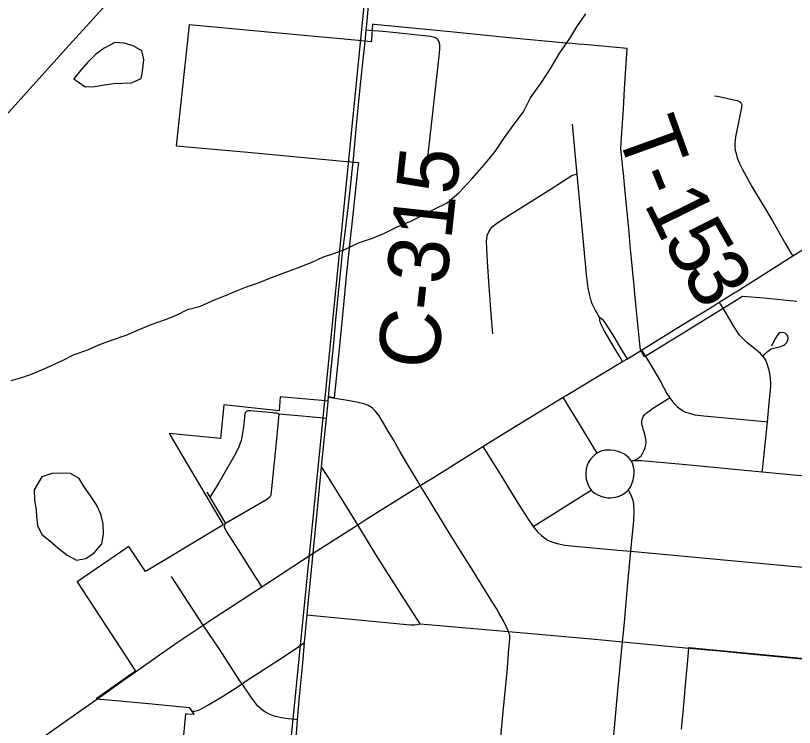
# Model space of a CAD drawing. Extents: x 0 to 34, y 0 to 22.
# Drawn here: x 2.542 to 3.271, y 14.717 to 15.383 of the extents above; entities that cross this region are included whole.
import ezdxf

# ---------------------------------------------------------------- set-up
doc = ezdxf.new("R2010")
doc.units = 0
for name, color, linetype in [('Default', 7, 'Continuous'), ('GM_X_City_Street', 7, 'Continuous'), ('GM_X_County_Road', 7, 'Continuous'), ('GM_X_County_Road_Text', 7, 'Continuous'), ('GM_X_Minor_Lake', 7, 'Continuous'), ('GM_X_Minor_River', 7, 'Continuous'), ('GM_X_Rail_Line', 7, 'Continuous'), ('GM_X_Section', 7, 'Continuous'), ('GM_X_Township_Road', 7, 'Continuous'), ('GM_X_Township_Road_Text', 7, 'Continuous'), ('SC_Shading1', 7, 'Continuous')]:
    doc.layers.add(name, color=color, linetype=linetype)

msp = doc.modelspace()

# ---------------------------------------------------------------- linework, layer by layer
at = {"layer": 'Default'}
msp.add_lwpolyline([(2.1, 15.58132), (2.1, 14.55888), (2.77821, 14.493), (2.87773, 15.48948)], close=True, dxfattribs=at)
at = {"layer": 'GM_X_City_Street'}
for p, q in [((2.72057, 14.93734), (2.72348, 14.93264)), ((2.72348, 14.93264), (2.73823, 14.90802))]:
    msp.add_line(p, q, dxfattribs=at)
for points in [[(2.86984, 15.36994), (2.87292, 15.36966), (2.88536, 15.36855), (2.89481, 15.36771), (2.92433, 15.36462), (2.93009, 15.3638), (2.93241, 15.36331), (2.93407, 15.36278)], [(2.92723, 15.24404), (2.92794, 15.25327), (2.93822, 15.34534), (2.93884, 15.35148), (2.93891, 15.35405), (2.93869, 15.35591), (2.93838, 15.35745), (2.9378, 15.35927), (2.93748, 15.35998), (2.93689, 15.36081), (2.93618, 15.36146), (2.93543, 15.36202), (2.93407, 15.36278)], [(3.08812, 15.10052), (3.0842, 15.10771), (3.0815, 15.11336), (3.08041, 15.1163), (3.07874, 15.12233), (3.07764, 15.12846), (3.07615, 15.14078), (3.07325, 15.1715), (3.06952, 15.21143), (3.06727, 15.23483), (3.0654, 15.25446), (3.06317, 15.27856), (3.06293, 15.28156)], [(2.98848, 15.08527), (2.98753, 15.09648), (2.98633, 15.11235), (2.98478, 15.13433), (2.98351, 15.15294), (2.98253, 15.17178), (2.98271, 15.17488), (2.98337, 15.1779), (2.98455, 15.18078), (2.98614, 15.18344), (2.98817, 15.18578), (2.99059, 15.18774), (2.99315, 15.1895), (3.00354, 15.19631), (3.04299, 15.22112), (3.06234, 15.2335), (3.06409, 15.23406), (3.0664, 15.23462), (3.06727, 15.23483)], [(3.24069, 14.95626), (3.24084, 14.95768), (3.2454, 15.00303), (3.24715, 15.02046), (3.24852, 15.03626), (3.24852, 15.03973), (3.24831, 15.043), (3.24811, 15.04658), (3.24705, 15.05122), (3.24631, 15.05427), (3.24537, 15.05723), (3.24389, 15.06059), (3.24273, 15.0626), (3.24126, 15.0646), (3.23907, 15.06686), (3.23512, 15.07016), (3.23091, 15.07344), (3.22577, 15.07766), (3.22182, 15.08148), (3.21945, 15.08398), (3.2164, 15.08841), (3.21366, 15.09294), (3.20589, 15.1064), (3.20234, 15.11189), (3.2004, 15.11488)], [(3.11438, 15.06209), (3.1119, 15.06606), (3.10866, 15.07124), (3.10071, 15.08459), (3.0932, 15.09626), (3.09202, 15.09776), (3.09035, 15.09911), (3.08812, 15.10052)], [(3.10983, 15.05936), (3.10722, 15.06384), (3.10207, 15.07268), (3.09573, 15.08312), (3.0927, 15.08851), (3.08987, 15.09424), (3.08889, 15.0965), (3.08846, 15.09806), (3.08812, 15.10052)], [(3.24126, 15.0646), (3.2451, 15.06842), (3.24679, 15.06979), (3.24822, 15.07092), (3.25029, 15.0716), (3.25409, 15.07252), (3.25766, 15.0736), (3.26015, 15.07454), (3.26165, 15.07535), (3.26271, 15.07628), (3.26365, 15.07741), (3.26434, 15.07897), (3.26475, 15.08066), (3.26484, 15.08166), (3.26447, 15.08309), (3.26353, 15.08453), (3.26196, 15.08584), (3.26071, 15.08641), (3.25915, 15.08665), (3.25721, 15.08634), (3.25578, 15.08541), (3.25447, 15.08378), (3.25297, 15.08141), (3.25141, 15.07847), (3.24922, 15.07379)], [(3.12772, 15.07008), (3.13604, 15.05669), (3.14529, 15.04074), (3.15138, 15.02966), (3.154, 15.02561), (3.15478, 15.0244), (3.15744, 15.02077), (3.16082, 15.01738), (3.16325, 15.01545), (3.16651, 15.01339), (3.16892, 15.01219), (3.1734, 15.01074), (3.17751, 15.00965), (3.18609, 15.00854), (3.24317, 15.00324), (3.2454, 15.00303)], [(2.92048, 14.9433), (2.91787, 14.94772), (2.90801, 14.96434), (2.9017, 14.97486), (2.89724, 14.98274), (2.89597, 14.98517), (2.89124, 14.99269), (2.88513, 15.00348), (2.88189, 15.0087), (2.87829, 15.0132), (2.87541, 15.01608), (2.87181, 15.01842), (2.86786, 15.01986), (2.86084, 15.02147), (2.85239, 15.02291), (2.84073, 15.02485), (2.83453, 15.02585)], [(3.08616, 14.97376), (3.08274, 14.97939), (3.0698, 15.0006), (3.05835, 15.01926), (3.05424, 15.02595)], [(3.11798, 14.9664), (3.12181, 14.96761), (3.12422, 14.96872), (3.12573, 14.96982), (3.12724, 14.97123), (3.12855, 14.97328), (3.12987, 14.97593), (3.13093, 14.97883), (3.13159, 14.98148), (3.13185, 14.98465), (3.13167, 14.98662), (3.13146, 14.98862), (3.13, 14.99347), (3.12921, 14.99615), (3.12867, 14.99792), (3.12815, 14.99959), (3.1279, 15.00126), (3.12785, 15.00278), (3.12796, 15.00382), (3.12832, 15.00534), (3.12885, 15.0067), (3.12952, 15.00821), (3.13062, 15.00978), (3.13159, 15.01083), (3.13313, 15.01219), (3.13883, 15.01604), (3.15049, 15.0234), (3.15195, 15.02431), (3.154, 15.02561)], [(2.78796, 15.01015), (2.7871, 15.01075), (2.78647, 15.01098), (2.78371, 15.01128), (2.78224, 15.01144), (2.77555, 15.01212), (2.76149, 15.01346), (2.76017, 15.01343), (2.7588, 15.01326), (2.75796, 15.01287), (2.75744, 15.01244), (2.75694, 15.01191), (2.75642, 15.01101), (2.75614, 15.01008), (2.75601, 15.009), (2.75588, 15.00738), (2.75502, 14.99799), (2.75352, 14.98861), (2.75271, 14.98551), (2.75053, 14.97951), (2.74778, 14.97378), (2.73205, 14.94653), (2.72709, 14.93849), (2.72348, 14.93264)], [(2.78796, 15.01015), (2.78553, 14.98359), (2.78452, 14.97444), (2.78355, 14.96526), (2.7811, 14.94063), (2.78062, 14.93426)], [(2.8325, 15.00606), (2.8298, 15.00632), (2.80622, 15.0085), (2.78796, 15.01015)], [(2.97905, 14.97987), (2.98214, 14.97494), (2.9969, 14.95145), (3.00649, 14.93554), (3.01297, 14.92502), (3.02136, 14.91201), (3.02617, 14.9051), (3.03017, 14.90011), (3.03398, 14.89653), (3.03672, 14.89451), (3.03934, 14.89272), (3.04172, 14.89129), (3.04535, 14.88999), (3.04863, 14.88915), (3.05578, 14.88772), (3.06471, 14.88664), (3.10564, 14.88299), (3.11769, 14.88194), (3.12074, 14.88168), (3.25836, 14.86879), (3.32859, 14.86219)], [(3.11552, 14.93953), (3.117, 14.94163), (3.11764, 14.94263), (3.11889, 14.94579), (3.11984, 14.94885), (3.12032, 14.95182), (3.12061, 14.95479), (3.12061, 14.95804), (3.12005, 14.96103), (3.11908, 14.96439), (3.11798, 14.9664), (3.11711, 14.96784), (3.11529, 14.96976), (3.11295, 14.97172), (3.11104, 14.97296), (3.10836, 14.9743), (3.10559, 14.97526), (3.10195, 14.97612), (3.09898, 14.9765), (3.0963, 14.9766), (3.09324, 14.97641), (3.08954, 14.97546), (3.08674, 14.97416), (3.08616, 14.97376), (3.0842, 14.97242), (3.08189, 14.97038), (3.08023, 14.96847), (3.07855, 14.96611), (3.07774, 14.96454), (3.0766, 14.96225), (3.07583, 14.95899), (3.07554, 14.95574), (3.07535, 14.95277), (3.07583, 14.94942), (3.07669, 14.94656), (3.07774, 14.94378), (3.07909, 14.94101), (3.0805, 14.93919), (3.08109, 14.93843), (3.08349, 14.93641), (3.08607, 14.93498), (3.08942, 14.93354), (3.09267, 14.93249), (3.09602, 14.93201), (3.0985, 14.93201), (3.1009, 14.93211), (3.10367, 14.93259), (3.10655, 14.93345), (3.10884, 14.9345), (3.11085, 14.93556), (3.11229, 14.93661), (3.11439, 14.93833), (3.11552, 14.93953)], [(3.11798, 14.9664), (3.12332, 14.9669), (3.12764, 14.96671), (3.13087, 14.96656), (3.13797, 14.96591), (3.16589, 14.96328), (3.24069, 14.95626), (3.33634, 14.94729), (3.3424, 14.94669), (3.38456, 14.94257), (3.39787, 14.94121), (3.40611, 14.94046), (3.46163, 14.9351), (3.46394, 14.93487)], [(2.86192, 14.90671), (2.85944, 14.91074), (2.8484, 14.92875), (2.83549, 14.94926), (2.83386, 14.9518), (2.82803, 14.96085)], [(2.99332, 14.6816), (2.99828, 14.73508), (3.0017, 14.76908), (3.0035, 14.79066), (3.00444, 14.79954), (3.00424, 14.80281), (3.00338, 14.80597), (3.00307, 14.80674), (3.00188, 14.80973), (2.99846, 14.81675), (2.99415, 14.82431), (2.99182, 14.82821), (2.98692, 14.83614), (2.96731, 14.86782), (2.96439, 14.87243), (2.95685, 14.88418), (2.94749, 14.89917), (2.92809, 14.93098), (2.92048, 14.9433)], [(3.02617, 14.9051), (3.02772, 14.90607), (3.07885, 14.93815), (3.0805, 14.93919)], [(3.08194, 14.4989), (3.08214, 14.50093), (3.08902, 14.57127), (3.08975, 14.57917), (3.09716, 14.65989), (3.09942, 14.68453), (3.1021, 14.71334), (3.10453, 14.74119), (3.10805, 14.77778), (3.10994, 14.79718), (3.11166, 14.81528), (3.11447, 14.84885), (3.11769, 14.88194), (3.11925, 14.89808), (3.12028, 14.91046), (3.12066, 14.91918), (3.12031, 14.92602), (3.11963, 14.9295), (3.11832, 14.93344), (3.11672, 14.9369), (3.11552, 14.93953)], [(2.78062, 14.93426), (2.77948, 14.9326), (2.7775, 14.93073), (2.73823, 14.90802)], [(2.77204, 14.84868), (2.76854, 14.85422), (2.7661, 14.85809), (2.75027, 14.88319), (2.74197, 14.89628), (2.7385, 14.90175), (2.73768, 14.90323), (2.73723, 14.90423), (2.73703, 14.90498), (2.73705, 14.90605), (2.73733, 14.90699), (2.73823, 14.90802)], [(2.92031, 14.8139), (2.90342, 14.84014), (2.88866, 14.8635), (2.87877, 14.87889), (2.86192, 14.90671)], [(2.71731, 14.81283), (2.70314, 14.83433), (2.69427, 14.8476), (2.68749, 14.85842)], [(2.8146, 14.82231), (2.82053, 14.82175), (2.89813, 14.81438), (2.90778, 14.81346), (2.91169, 14.81314), (2.91506, 14.81314), (2.91757, 14.81336), (2.92031, 14.8139)], [(2.80562, 14.72418), (2.8035, 14.7244), (2.79666, 14.72509), (2.79042, 14.72606), (2.78484, 14.72725), (2.78128, 14.72858), (2.77842, 14.7298), (2.77568, 14.73126), (2.77309, 14.73298), (2.77068, 14.73493), (2.76844, 14.7371), (2.76638, 14.73943), (2.76265, 14.74439), (2.75354, 14.7579), (2.75223, 14.75985), (2.73184, 14.79108), (2.71731, 14.81283)], [(2.92031, 14.8139), (3.00307, 14.80674), (3.04551, 14.8031), (3.0874, 14.79929), (3.10994, 14.79718), (3.17227, 14.79122)], [(2.7064, 14.73215), (2.70918, 14.73227), (2.71185, 14.73285), (2.7144, 14.73378), (2.72102, 14.73761), (2.73367, 14.74515), (2.7447, 14.752), (2.75354, 14.7579), (2.75661, 14.75994), (2.78811, 14.78044), (2.80352, 14.79075), (2.81219, 14.79654)]]:
    msp.add_lwpolyline(points, dxfattribs=at)
at = {"layer": 'GM_X_County_Road'}
for p, q in [((3.11438, 15.06209), (3.12772, 15.07008)), ((3.10983, 15.05936), (3.11438, 15.06209)), ((2.83431, 15.02383), (2.83453, 15.02585)), ((2.82023, 14.88026), (2.86192, 14.90671)), ((2.77204, 14.84868), (2.82023, 14.88026)), ((2.81219, 14.79654), (2.8146, 14.82231))]:
    msp.add_line(p, q, dxfattribs=at)
for points in [[(3.26918, 15.15837), (3.3118, 15.18484), (3.33823, 15.20119), (3.36749, 15.21887), (3.39692, 15.23621), (3.42364, 15.25205), (3.47295, 15.28086), (3.48991, 15.29036), (3.55312, 15.32589), (3.64279, 15.37547), (3.66715, 15.38906), (3.7813, 15.45258), (3.84384, 15.48767), (3.90317, 15.52055), (3.90579, 15.522)], [(2.86984, 15.36994), (2.87032, 15.37487), (2.87319, 15.40688), (2.87706, 15.44438)], [(2.86704, 15.3421), (2.86875, 15.35876), (2.86984, 15.36994)], [(2.85739, 15.24364), (2.85761, 15.24563), (2.86114, 15.2839), (2.86203, 15.29344), (2.86368, 15.30926), (2.86493, 15.32152), (2.86704, 15.3421)], [(2.8531, 15.20589), (2.85478, 15.21985), (2.85739, 15.24364)], [(2.83942, 15.0766), (2.84153, 15.09883), (2.84528, 15.13599), (2.84777, 15.16081), (2.84998, 15.17996), (2.8531, 15.20589)], [(3.2004, 15.11488), (3.21508, 15.12397), (3.21612, 15.12464), (3.26225, 15.15407), (3.26918, 15.15837)], [(3.12772, 15.07008), (3.16733, 15.09457), (3.1936, 15.11068), (3.2004, 15.11488)], [(2.83453, 15.02585), (2.83547, 15.03662), (2.83855, 15.06751), (2.83942, 15.0766)], [(3.05424, 15.02595), (3.05697, 15.02761), (3.10983, 15.05936)], [(2.8325, 15.00606), (2.8341, 15.02181), (2.83431, 15.02383)], [(2.97905, 14.97987), (2.99968, 14.9927), (3.05424, 15.02595)], [(2.82803, 14.96085), (2.83069, 14.98833), (2.8325, 15.00606)], [(2.92048, 14.9433), (2.93289, 14.951), (2.97905, 14.97987)], [(2.82023, 14.88026), (2.8239, 14.91806), (2.82803, 14.96085)], [(2.86192, 14.90671), (2.87044, 14.91212), (2.92048, 14.9433)], [(2.8146, 14.82231), (2.81589, 14.83611), (2.82023, 14.88026)], [(2.71731, 14.81283), (2.72761, 14.81957), (2.77204, 14.84868)], [(2.68645, 14.79208), (2.69279, 14.79649), (2.71731, 14.81283)], [(2.80562, 14.72418), (2.80745, 14.74613), (2.8104, 14.7773), (2.81219, 14.79654)], [(2.64252, 14.76123), (2.64661, 14.76415), (2.6538, 14.76917), (2.67615, 14.78491), (2.68645, 14.79208)], [(2.60082, 14.73164), (2.61715, 14.74311), (2.64252, 14.76123)], [(2.54356, 14.69123), (2.56895, 14.70926), (2.60082, 14.73164)], [(2.80207, 14.68639), (2.80487, 14.71506), (2.80562, 14.72418)]]:
    msp.add_lwpolyline(points, dxfattribs=at)
at = {"layer": 'GM_X_Minor_Lake'}
for points in [[(2.65993, 15.32889), (2.66077, 15.33374), (2.66164, 15.34208), (2.65983, 15.35008), (2.65153, 15.35474), (2.64321, 15.3575), (2.63448, 15.35799), (2.62454, 15.3528), (2.61649, 15.34682), (2.60918, 15.3397), (2.60225, 15.33181), (2.59607, 15.32391)], [(2.59607, 15.32391), (2.60662, 15.31657), (2.61574, 15.31684), (2.62449, 15.31825), (2.63363, 15.31965), (2.64161, 15.31993), (2.64997, 15.32021), (2.65914, 15.32427), (2.65993, 15.32889)], [(2.56603, 14.95146), (2.55904, 14.93939), (2.5593, 14.9299), (2.56071, 14.92039), (2.56102, 14.91469), (2.56205, 14.90595), (2.56612, 14.89754), (2.57365, 14.89175), (2.58117, 14.88521), (2.58982, 14.87826), (2.5985, 14.8736), (2.60401, 14.87449)], [(2.60401, 14.87449), (2.60725, 14.87501), (2.6153, 14.88061), (2.62224, 14.88887), (2.62387, 14.89796), (2.62361, 14.90746), (2.62144, 14.9166), (2.61737, 14.92538), (2.61178, 14.9338), (2.6058, 14.94223), (2.60096, 14.94988), (2.59304, 14.95454), (2.58317, 14.95504), (2.57557, 14.95475), (2.56603, 14.95146)]]:
    msp.add_lwpolyline(points, dxfattribs=at)
at = {"layer": 'GM_X_Minor_River'}
msp.add_lwpolyline([(2.53751, 15.04179), (2.54818, 15.04469), (2.55811, 15.04837), (2.57109, 15.0539), (2.58561, 15.06056), (2.59631, 15.06612), (2.60928, 15.07051), (2.61959, 15.07494), (2.63143, 15.07935), (2.64516, 15.08412), (2.65509, 15.08855), (2.66846, 15.09408), (2.68181, 15.09885), (2.69212, 15.10289), (2.70244, 15.10808), (2.71464, 15.11135), (2.72763, 15.11726), (2.73793, 15.12131), (2.74824, 15.12574), (2.75779, 15.12942), (2.76885, 15.13307), (2.77954, 15.1375), (2.79442, 15.14301), (2.80549, 15.14705), (2.81923, 15.15257), (2.82993, 15.15737), (2.83947, 15.16067), (2.85053, 15.16471), (2.86276, 15.17063), (2.87573, 15.17503), (2.88681, 15.17945), (2.89866, 15.18537), (2.91164, 15.19091), (2.92158, 15.19572), (2.93343, 15.20203), (2.94566, 15.20795), (2.9568, 15.21768), (2.96912, 15.23082), (2.98067, 15.24396), (2.9907, 15.25599), (2.99922, 15.26917), (3.00849, 15.28159), (3.01699, 15.29325), (3.02361, 15.30608), (3.03443, 15.32151), (3.04295, 15.3347), (3.0511, 15.34826), (3.06038, 15.36182), (3.06698, 15.37275), (3.07548, 15.38479)], dxfattribs=at)
at = {"layer": 'GM_X_Rail_Line'}
msp.add_lwpolyline([(2.1, 14.81172), (2.21342, 14.93725), (2.27041, 15.00196), (2.29876, 15.03142), (2.33999, 15.07735), (2.43241, 15.17961), (2.5269, 15.28373), (2.5887, 15.3522), (2.6494, 15.41902), (2.66788, 15.43827), (2.7067, 15.47633), (2.73284, 15.50225), (2.77572, 15.53539), (2.80161, 15.55513), (2.84301, 15.58439), (2.90313, 15.62543), (2.932, 15.64588)], dxfattribs=at)
at = {"layer": 'GM_X_Section'}
msp.add_lwpolyline([(2.87773, 15.48948), (3.88999, 15.39575), (3.78848, 14.39294), (2.80014, 14.49076), (2.77821, 14.493)], close=True, dxfattribs=at)
at = {"layer": 'GM_X_Township_Road'}
for points in [[(3.19592, 15.30819), (3.19841, 15.30779), (3.20161, 15.30722), (3.21686, 15.3038), (3.21932, 15.30285), (3.22052, 15.30171), (3.22117, 15.30074), (3.22149, 15.29937), (3.22127, 15.29709), (3.21856, 15.28487), (3.21732, 15.27878), (3.21558, 15.26958), (3.21503, 15.26336), (3.21504, 15.26023), (3.21538, 15.25714), (3.21606, 15.25409), (3.21695, 15.25109), (3.21912, 15.24528), (3.22183, 15.23969), (3.23103, 15.22337), (3.25021, 15.19119), (3.26253, 15.16948), (3.26785, 15.16059), (3.26918, 15.15837)], [(3.17227, 14.79122), (3.20081, 14.7886), (3.22554, 14.7862), (3.26454, 14.7825), (3.32699, 14.77676)]]:
    msp.add_lwpolyline(points, dxfattribs=at)
at = {"layer": 'SC_Shading1'}
for points in [[(3.27309, 15.11577), (3.24203, 15.11859), (3.22211, 15.12041), (3.21209, 15.11404), (3.19607, 15.10408), (3.168, 15.0869), (3.13966, 15.06957), (3.13046, 15.06394), (3.1265, 15.07041), (3.1257, 15.07879), (3.12242, 15.11301), (3.12149, 15.12261), (3.12073, 15.13054), (3.11925, 15.14601), (3.11743, 15.16486), (3.11562, 15.18371), (3.11381, 15.20256), (3.112, 15.22142), (3.11062, 15.23573), (3.11019, 15.24027), (3.10837, 15.25912), (3.10956, 15.27826), (3.11064, 15.2957), (3.11181, 15.3146), (3.11299, 15.33351), (3.11416, 15.35243), (3.07396, 15.356), (3.06833, 15.3565), (3.06264, 15.357), (3.05379, 15.35779), (3.0068, 15.36196), (2.94519, 15.36823), (2.8774, 15.37489), (2.8758, 15.37505), (2.87469, 15.36088), (2.87448, 15.35874), (2.86825, 15.35931), (2.8626, 15.35983), (2.76072, 15.36921), (2.70413, 15.37442), (2.69187, 15.26143), (2.74846, 15.25622), (2.75902, 15.25524), (2.85126, 15.24676), (2.86258, 15.24572), (2.86175, 15.23808), (2.85602, 15.18527), (2.85516, 15.17737), (2.85118, 15.13935), (2.84849, 15.11239), (2.84468, 15.07405), (2.84163, 15.04348), (2.83985, 15.02559), (2.83436, 15.02646), (2.83399, 15.02237), (2.82833, 15.02289), (2.7925, 15.02616), (2.78939, 15.02644), (2.7882, 15.01346), (2.77377, 15.01497), (2.7364, 15.01887), (2.73326, 14.98736), (2.68533, 14.99201), (2.73603, 14.90669), (2.73199, 14.90409), (2.70425, 14.88753), (2.68009, 14.87309), (2.66323, 14.86302), (2.64755, 14.88642), (2.59916, 14.85339), (2.63031, 14.8056), (2.64965, 14.77593), (2.65369, 14.76973), (2.65058, 14.76754), (2.61699, 14.74389), (2.62855, 14.7428), (2.66944, 14.73902), (2.70421, 14.7358), (2.7057, 14.73355), (2.70831, 14.7296), (2.70868, 14.72904), (2.70276, 14.72956), (2.70065, 14.72975), (2.69853, 14.70624)], [(3.16507, 14.7155), (3.16678, 14.73436), (3.16848, 14.75323), (3.17155, 14.78714), (3.17204, 14.79176), (3.3265, 14.77715)]]:
    msp.add_lwpolyline(points, dxfattribs=at)

# ---------------------------------------------------------------- texts
at = {"layer": 'GM_X_County_Road_Text'}
msp.add_text('C-315', height=0.056818, rotation=83.87478, dxfattribs=at).set_placement((2.93637, 15.05067))
at = {"layer": 'GM_X_Township_Road_Text'}
for s, rotation, p in [('T', 289.81945, (3.10347, 15.27546)), ('-', 292.05611, (3.11874, 15.23322)), ('1', 296.31147, (3.12939, 15.2074)), ('5', 299.81986, (3.14669, 15.17268)), ('3', 300.27638, (3.16434, 15.14188))]:
    msp.add_text(s, height=0.05682, rotation=rotation, dxfattribs=at).set_placement(p)

doc.saveas('drawing.dxf')
